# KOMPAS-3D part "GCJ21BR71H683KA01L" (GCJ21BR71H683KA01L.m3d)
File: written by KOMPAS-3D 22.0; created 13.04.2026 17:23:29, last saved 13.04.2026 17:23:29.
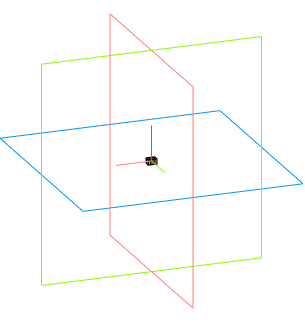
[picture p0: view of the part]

Document properties: Автор: Andrey; Полное имя файла: C:\Users\User1\Documents\GCJ21BR71H683KA01L.m3d

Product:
- Part/product: GCJ21BR71H683KA01L

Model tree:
1. Операция без истории:1
2. Операция без истории:2
3. Операция без истории:3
